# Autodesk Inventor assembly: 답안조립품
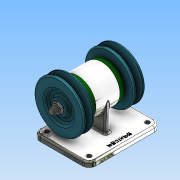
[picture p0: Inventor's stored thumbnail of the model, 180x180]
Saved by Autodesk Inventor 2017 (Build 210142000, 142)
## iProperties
Part Number: 답안조립품
Material: 일반
Document SubType Name: Assembly
Designer: 603-10
Author: 603-10
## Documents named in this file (10)
- C:\Users\603-10\Desktop\490904V1041\답안조립품.iam
- C:\Users\603-10\Desktop\490904V1041\본체.ipt
- C:\Users\603-10\Desktop\490904V1041\V-벨트풀리.ipt
- C:\Users\603-10\Desktop\490904V1041\너트 M10x1.ipt
- C:\Users\603-10\Desktop\490904V1041\베어링 6004.ipt
- C:\Users\603-10\Desktop\490904V1041\볼트 M4.ipt
- C:\Users\603-10\Desktop\490904V1041\오일 실 17 30 5.ipt
- C:\Users\603-10\Desktop\490904V1041\축.ipt
- C:\Users\603-10\Desktop\490904V1041\커버.ipt
- C:\Users\603-10\Desktop\490904V1041\키 5 x 5 x 12.ipt
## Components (2 placed, 1 different names)
1. V-벨트풀리:1
2. V-벨트풀리:2
